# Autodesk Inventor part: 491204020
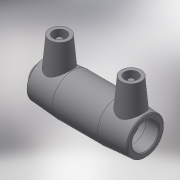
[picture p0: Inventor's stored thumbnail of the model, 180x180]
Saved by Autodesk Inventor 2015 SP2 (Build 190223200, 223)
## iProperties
Created: 2017-06
Part Number: 491204020
Material: Generic
Description: PLASSON END CAP 20
Document SubType Name: Modeling
Designer: KIM
Mass: 38.9236 g
Surface Area: 152.394 cm^2
Volume: 38.9236 cm^3
Density: 1 g/cm^3
Appearance: Default
Author: KIM
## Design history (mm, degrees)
derived "491204.ipt"
feature "Solid1::491204.ipt"
tag "TaggingFeature1"
body "Solid1"
other parameters: "d0" = 76, "d2" = 31, "d3" = 37, "d4" = 21, "d5" = 27.9, "d6" = 19, "d8" = 168 deg, "d10" = 14.8, "d11" = 4.93333, "d13" = 67.2, "d14" = 17.6296, "d15" = 37, "d16" = 37, "d17" = 19, "d19" = 3.52592, "d20" = 168 deg, "d22" = 29.14, "d23" = 31, "d24" = 28.2658, "d25" = 135 deg, "d26" = 30.24, "d27" = 135 deg, "d29" = 34, "d30" = 15, "d31" = 26.88, "d34" = 5 deg, "d35" = 15, "d39" = 5 deg, "d41" = 4, "d42" = 14, "d43" = 0, "d45" = 4, "d46" = 14, "d47" = 0, "d48" = 84, "d49" = 1, "d51" = 16, "d52" = 1.512, "d53" = 22, "d54" = 1.512, "d56" = 2, "d57" = 0.6, "d60" = 12.6, "d61" = 0.4, "d63" = 84, "d64" = 1, "d66" = 16, "d67" = 4, "d68" = 22, "d69" = 1.68, "d70" = 0, "d71" = 1.512, "d72" = 3, "d73" = 0, "d74" = 10.73, "d75" = 3.57667, "d76" = 3, "d77" = 0, "L_" = 84, "L_1" = 37, "D_" = 31, "A_" = 34, "d_2" = 12, "L_0" = 76, "d55" = 2
